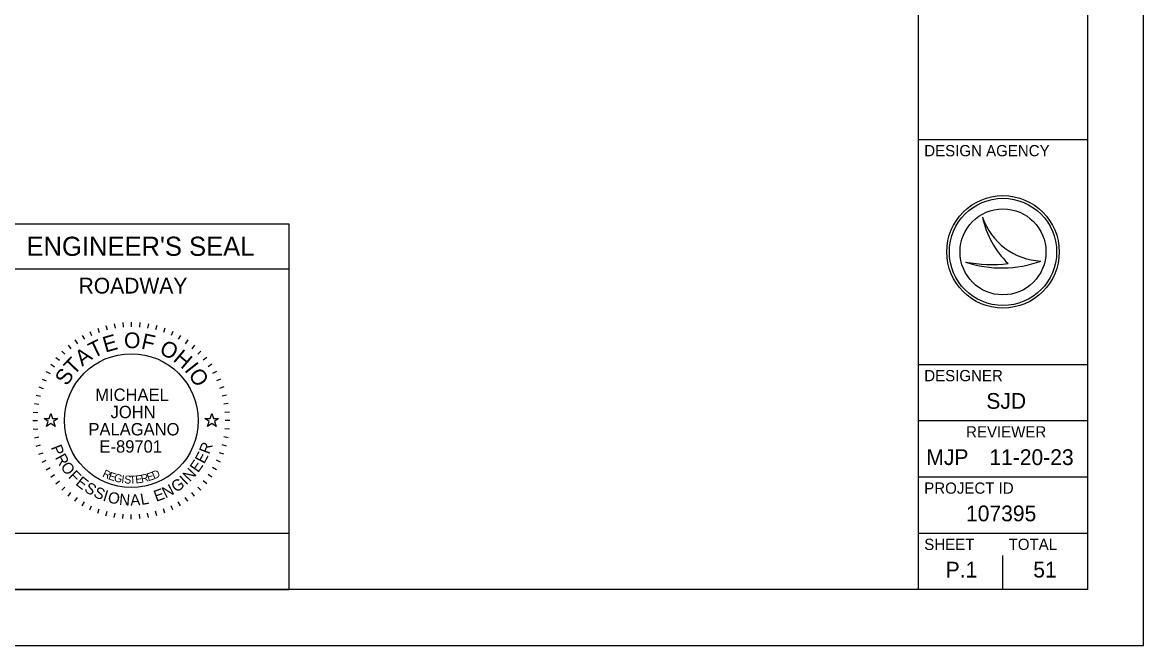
# Model space of a CAD drawing. Extents: x 0 to 34, y 0 to 22.
# Drawn here: x 24.03 to 34, y 0 to 5.54 of the extents above; entities that cross this region are included whole.
import ezdxf

# ---------------------------------------------------------------- set-up
doc = ezdxf.new("R2010")
doc.units = 0
for name, color, linetype in [('Default', 7, 'Continuous'), ('SH_Border', 7, 'Continuous'), ('SH_Cut_Line', 7, 'Continuous'), ('SH_Data', 7, 'Continuous')]:
    doc.layers.add(name, color=color, linetype=linetype)

msp = doc.modelspace()

# ---------------------------------------------------------------- linework, layer by layer
at = {"layer": 'Default'}
for points in [[(24.2236, 2.02), (24.2705, 2.02), (24.285, 2.0645), (24.2995, 2.02), (24.3464, 2.02), (24.3085, 1.9924), (24.323, 1.9478), (24.285, 1.9754), (24.247, 1.9478), (24.2615, 1.9924)], [(25.6536, 2.02), (25.7005, 2.02), (25.715, 2.0645), (25.7295, 2.02), (25.7764, 2.02), (25.7385, 1.9924), (25.753, 1.9478), (25.715, 1.9754), (25.677, 1.9478), (25.6915, 1.9924)]]:
    msp.add_lwpolyline(points, close=True, dxfattribs=at)
at = {"layer": 'SH_Border'}
for p, q in [((32, 0.5), (32, 21.5)), ((32, 4.5), (33.5, 4.5)), ((32, 2.5), (33.5, 2.5)), ((32, 2), (33.5, 2)), ((32, 1.5), (33.5, 1.5)), ((32, 1), (33.5, 1))]:
    msp.add_line(p, q, dxfattribs=at)
msp.add_lwpolyline([(1.5, 21.5), (33.5, 21.5), (33.5, 0.5), (1.5, 0.5)], close=True, dxfattribs=at)
at = {"layer": 'SH_Cut_Line'}
msp.add_lwpolyline([(0, 0), (34, 0), (34, 22), (0, 22)], close=True, dxfattribs=at)
at = {"layer": 'SH_Data'}
for p, q in [((32.5674, 3.8096), (32.5675, 3.8096)), ((23.6, 3.75), (26.4, 3.75)), ((26.4, 3.75), (26.4, 0.5)), ((32.75, 3.5), (32.75, 3.5)), ((32.4172, 3.4095), (32.4172, 3.4095)), ((33.0873, 3.4185), (33.0873, 3.4185)), ((23.6, 3.35), (26.4, 3.35)), ((24.6302, 2.793), (24.6471, 2.7568)), ((24.7007, 2.8222), (24.7144, 2.7846)), ((24.7735, 2.8452), (24.7839, 2.8065)), ((24.8481, 2.8617), (24.855, 2.8223)), ((24.9237, 2.8717), (24.9272, 2.8318)), ((25, 2.875), (25, 2.835)), ((25.0763, 2.8717), (25.0728, 2.8318)), ((25.1519, 2.8617), (25.145, 2.8223)), ((25.2265, 2.8452), (25.2161, 2.8065)), ((25.2993, 2.8222), (25.2856, 2.7846)), ((25.3698, 2.793), (25.3529, 2.7568)), ((24.4981, 2.7168), (24.5211, 2.684)), ((24.5625, 2.7578), (24.5825, 2.7231)), ((25.4375, 2.7578), (25.4175, 2.7231)), ((25.5019, 2.7168), (25.4789, 2.684)), ((24.3813, 2.6187), (24.4096, 2.5904)), ((24.4376, 2.6703), (24.4633, 2.6396)), ((25.5624, 2.6703), (25.5367, 2.6396)), ((25.6187, 2.6187), (25.5904, 2.5904)), ((24.2832, 2.5019), (24.316, 2.4789)), ((24.3297, 2.5624), (24.3604, 2.5367)), ((25.6703, 2.5624), (25.6396, 2.5367)), ((25.7168, 2.5019), (25.684, 2.4789)), ((24.2422, 2.4375), (24.2769, 2.4175)), ((25.7578, 2.4375), (25.7231, 2.4175)), ((24.1778, 2.2993), (24.2154, 2.2856)), ((24.207, 2.3698), (24.2432, 2.3529)), ((25.793, 2.3698), (25.7568, 2.3529)), ((25.8222, 2.2993), (25.7846, 2.2856)), ((24.1548, 2.2265), (24.1935, 2.2161)), ((25.8452, 2.2265), (25.8065, 2.2161)), ((24.1383, 2.1519), (24.1777, 2.145)), ((25.8617, 2.1519), (25.8223, 2.145)), ((24.125, 2), (24.165, 2)), ((24.1283, 2.0763), (24.1682, 2.0728)), ((25.8717, 2.0763), (25.8318, 2.0728)), ((25.875, 2), (25.835, 2)), ((24.1283, 1.9237), (24.1682, 1.9272)), ((25.8717, 1.9237), (25.8318, 1.9272)), ((24.1383, 1.8481), (24.1777, 1.855)), ((25.8617, 1.8481), (25.8223, 1.855)), ((24.1548, 1.7735), (24.1935, 1.7839)), ((24.1778, 1.7007), (24.2154, 1.7144)), ((25.8222, 1.7007), (25.7846, 1.7144)), ((25.8452, 1.7735), (25.8065, 1.7839)), ((24.207, 1.6302), (24.2432, 1.6471)), ((25.793, 1.6302), (25.7568, 1.6471)), ((24.2422, 1.5625), (24.2769, 1.5825)), ((24.2832, 1.4981), (24.316, 1.5211)), ((25.7168, 1.4981), (25.684, 1.5211)), ((25.7578, 1.5625), (25.7231, 1.5825)), ((24.3297, 1.4376), (24.3604, 1.4633)), ((24.3813, 1.3813), (24.4096, 1.4096)), ((25.6187, 1.3813), (25.5904, 1.4096)), ((25.6703, 1.4376), (25.6396, 1.4633)), ((24.4376, 1.3297), (24.4633, 1.3604)), ((24.4981, 1.2832), (24.5211, 1.316)), ((25.5019, 1.2832), (25.4789, 1.316)), ((25.5624, 1.3297), (25.5367, 1.3604)), ((24.5625, 1.2422), (24.5825, 1.2769)), ((24.6302, 1.207), (24.6471, 1.2432)), ((24.7007, 1.1778), (24.7144, 1.2154)), ((25.2993, 1.1778), (25.2856, 1.2154)), ((25.3698, 1.207), (25.3529, 1.2432)), ((25.4375, 1.2422), (25.4175, 1.2769)), ((24.7735, 1.1548), (24.7839, 1.1935)), ((24.8481, 1.1383), (24.855, 1.1777)), ((24.9237, 1.1283), (24.9272, 1.1682)), ((25, 1.125), (25, 1.165)), ((25.0763, 1.1283), (25.0728, 1.1682)), ((25.1519, 1.1383), (25.145, 1.1777)), ((25.2265, 1.1548), (25.2161, 1.1935)), ((32.75, 0.5), (32.75, 0.8)), ((32.375, 0.675), (32.375, 0.675)), ((23.6, 0.5), (26.4, 0.5)), ((23.6, 0.5), (26.4, 0.5))]:
    msp.add_line(p, q, dxfattribs=at)
msp.add_lwpolyline([(23.6, 0.5), (23.6, 1), (26.4, 1), (26.4, 0.5)], close=True, dxfattribs=at)
for centre, radius in [((32.75, 3.5), 0.5), ((32.75, 3.5), 0.4768), ((32.75, 3.5), 0.4768), ((32.75, 3.5), 0.3822), ((25, 2), 0.595)]:
    msp.add_circle(centre, radius, dxfattribs=at)
for centre, radius, start, end in [((33.1159, 3.9976), 0.5798, 198.92567, 198.93195), ((33.3467, 3.9701), 0.7956, 191.63793, 191.64215), ((33.1159, 3.9976), 0.5798, 198.93195, 267.16574), ((33.3467, 3.9701), 0.7956, 191.64215, 226.09467), ((32.7394, 4.37), 1.0131, 251.45764, 290.08324), ((32.648, 4.6543), 1.2661, 259.49639, 259.49952), ((32.7394, 4.37), 1.0131, 251.45274, 251.45764), ((32.648, 4.6543), 1.2661, 259.49952, 276.66723)]:
    msp.add_arc(centre, radius, start, end, dxfattribs=at)

# ---------------------------------------------------------------- texts
for s, height, p in [('DESIGN AGENCY', 0.1, (32.05, 4.35)), ("ENGINEER'S SEAL", 0.17, (24.0676, 3.465)), ('ROADWAY', 0.14, (24.5311, 3.13)), ('DESIGNER', 0.1, (32.05, 2.35)), ('MICHAEL', 0.11, (24.6789, 2.1749)), ('SJD', 0.14, (32.6018, 2.105)), ('JOHN', 0.11, (24.8153, 2.0216)), ('PALAGANO', 0.11, (24.6186, 1.8684)), ('REVIEWER', 0.1, (32.4218, 1.85)), ('E-89701', 0.11, (24.7167, 1.7151)), ('MJP', 0.14, (32.0685, 1.605)), ('11-20-23', 0.14, (32.6289, 1.605)), ('PROJECT ID', 0.1, (32.05, 1.35)), ('107395', 0.14, (32.4212, 1.105)), ('SHEET', 0.1, (32.05, 0.85)), ('TOTAL', 0.1, (32.8, 0.85)), ('P.1', 0.14, (32.2403, 0.605)), ('51', 0.14, (33.0192, 0.605))]:
    msp.add_text(s, height=height, dxfattribs=at).set_placement(p)
for s, height, rotation, p in [('T', 0.14, 25.71674, (24.6616, 2.5518)), ('E', 0.14, 15.75706, (24.7684, 2.6038)), ('O', 0.14, 359.78119, (24.9347, 2.6443)), ('F', 0.14, 347.43619, (25.0811, 2.6417)), ('O', 0.14, 332.25863, (25.2398, 2.6015)), ('A', 0.14, 36.47472, (24.5634, 2.4781)), ('H', 0.14, 319.91363, (25.3632, 2.5361)), ('T', 0.14, 46.4344, (24.4883, 2.3964)), ('I', 0.14, 308.36695, (25.4665, 2.4483)), ('S', 0.14, 57.19238, (24.4281, 2.3014)), ('O', 0.14, 303.14906, (25.5021, 2.4089)), ('R', 0.1, 69.23216, (25.6919, 1.6954)), ('P', 0.1, 291.49398, (24.2823, 1.7621)), ('R', 0.1, 298.73106, (24.319, 1.6717)), ('E', 0.1, 61.99508, (25.6476, 1.6098)), ('O', 0.1, 306.46664, (24.3655, 1.5883)), ('E', 0.1, 54.75801, (25.5933, 1.5314)), ('F', 0.1, 314.7068, (24.4343, 1.4983)), ('E', 0.1, 321.43929, (24.4978, 1.4348)), ('R', 0.07, 334.48695, (24.7375, 1.5051)), ('E', 0.07, 341.03996, (24.7906, 1.4801)), ('G', 0.07, 347.47515, (24.8414, 1.4618)), ('I', 0.07, 353.78581, (24.9091, 1.4468)), ('S', 0.07, 356.89262, (24.9358, 1.4429)), ('T', 0.07, 3.00609, (24.9857, 1.4387)), ('E', 0.07, 6.01169, (25.0389, 1.4412)), ('R', 0.07, 11.91844, (25.0925, 1.4474)), ('E', 0.07, 17.68363, (25.1498, 1.4602)), ('D', 0.07, 23.30524, (25.201, 1.477)), ('I', 0.1, 43.28703, (25.4868, 1.4214)), ('N', 0.1, 47.02243, (25.5202, 1.4508)), ('S', 0.1, 328.67637, (24.5743, 1.3752)), ('S', 0.1, 335.91345, (24.6564, 1.3266)), ('E', 0.1, 20.07421, (25.2212, 1.277)), ('N', 0.1, 27.31129, (25.3045, 1.3075)), ('G', 0.1, 35.04687, (25.3981, 1.357)), ('I', 0.1, 343.15053, (24.7406, 1.2897)), ('O', 0.1, 346.88592, (24.7839, 1.2751)), ('N', 0.1, 355.12608, (24.8888, 1.2517)), ('A', 0.1, 2.86166, (24.9923, 1.2437)), ('L', 0.1, 10.09874, (25.0894, 1.249))]:
    msp.add_text(s, height=height, rotation=rotation, dxfattribs=at).set_placement(p)

doc.saveas('drawing.dxf')
